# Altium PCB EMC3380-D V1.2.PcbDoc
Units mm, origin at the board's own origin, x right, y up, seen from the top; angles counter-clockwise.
Board outline 20 x 33 mm, 2 copper layers (Top Layer, Bottom Layer); 70 components, 71 nets, 338 pads, 271 vias.
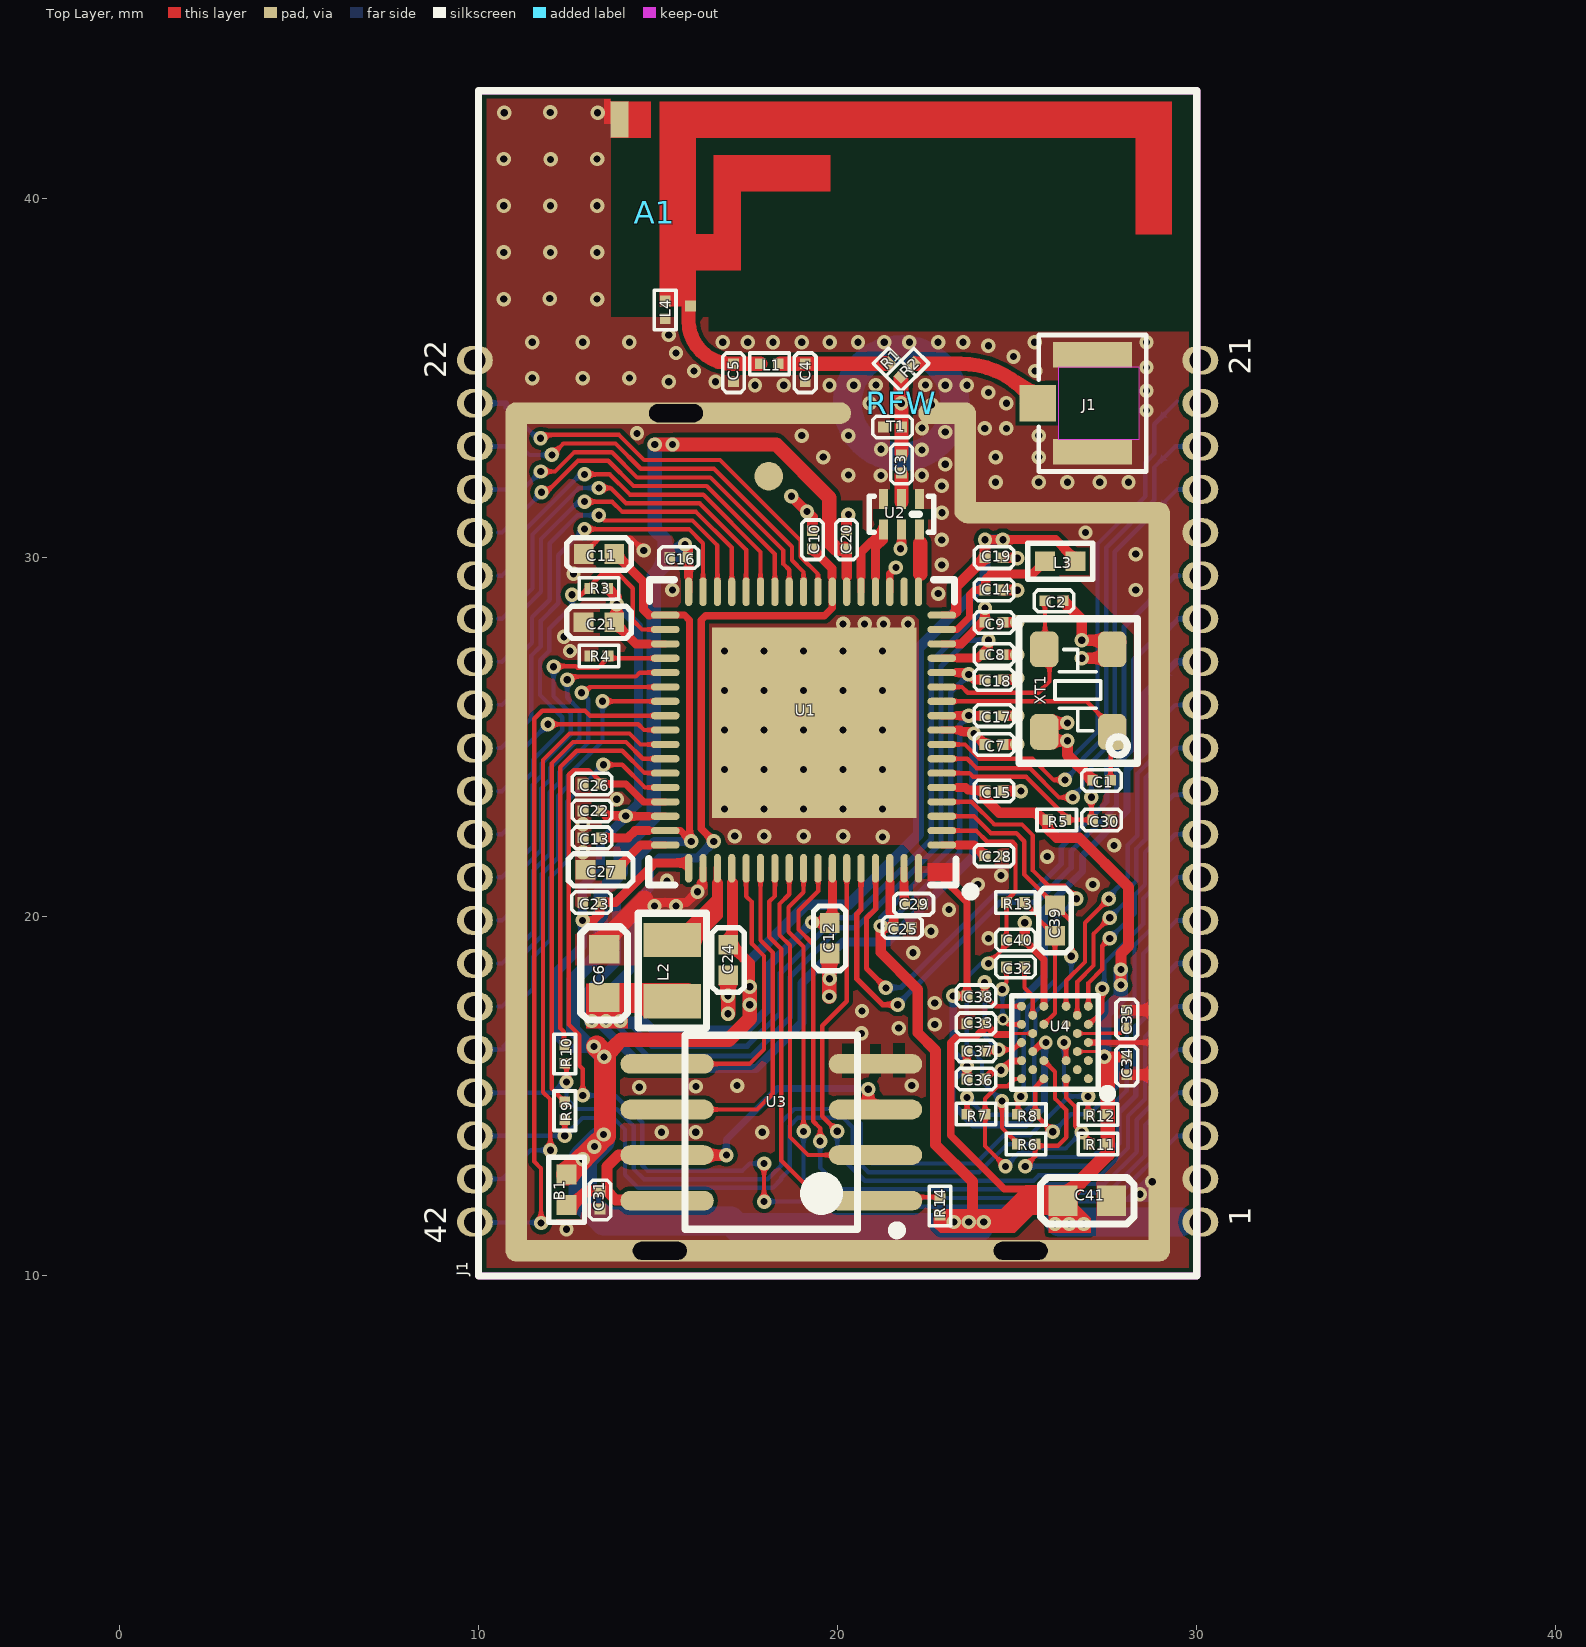
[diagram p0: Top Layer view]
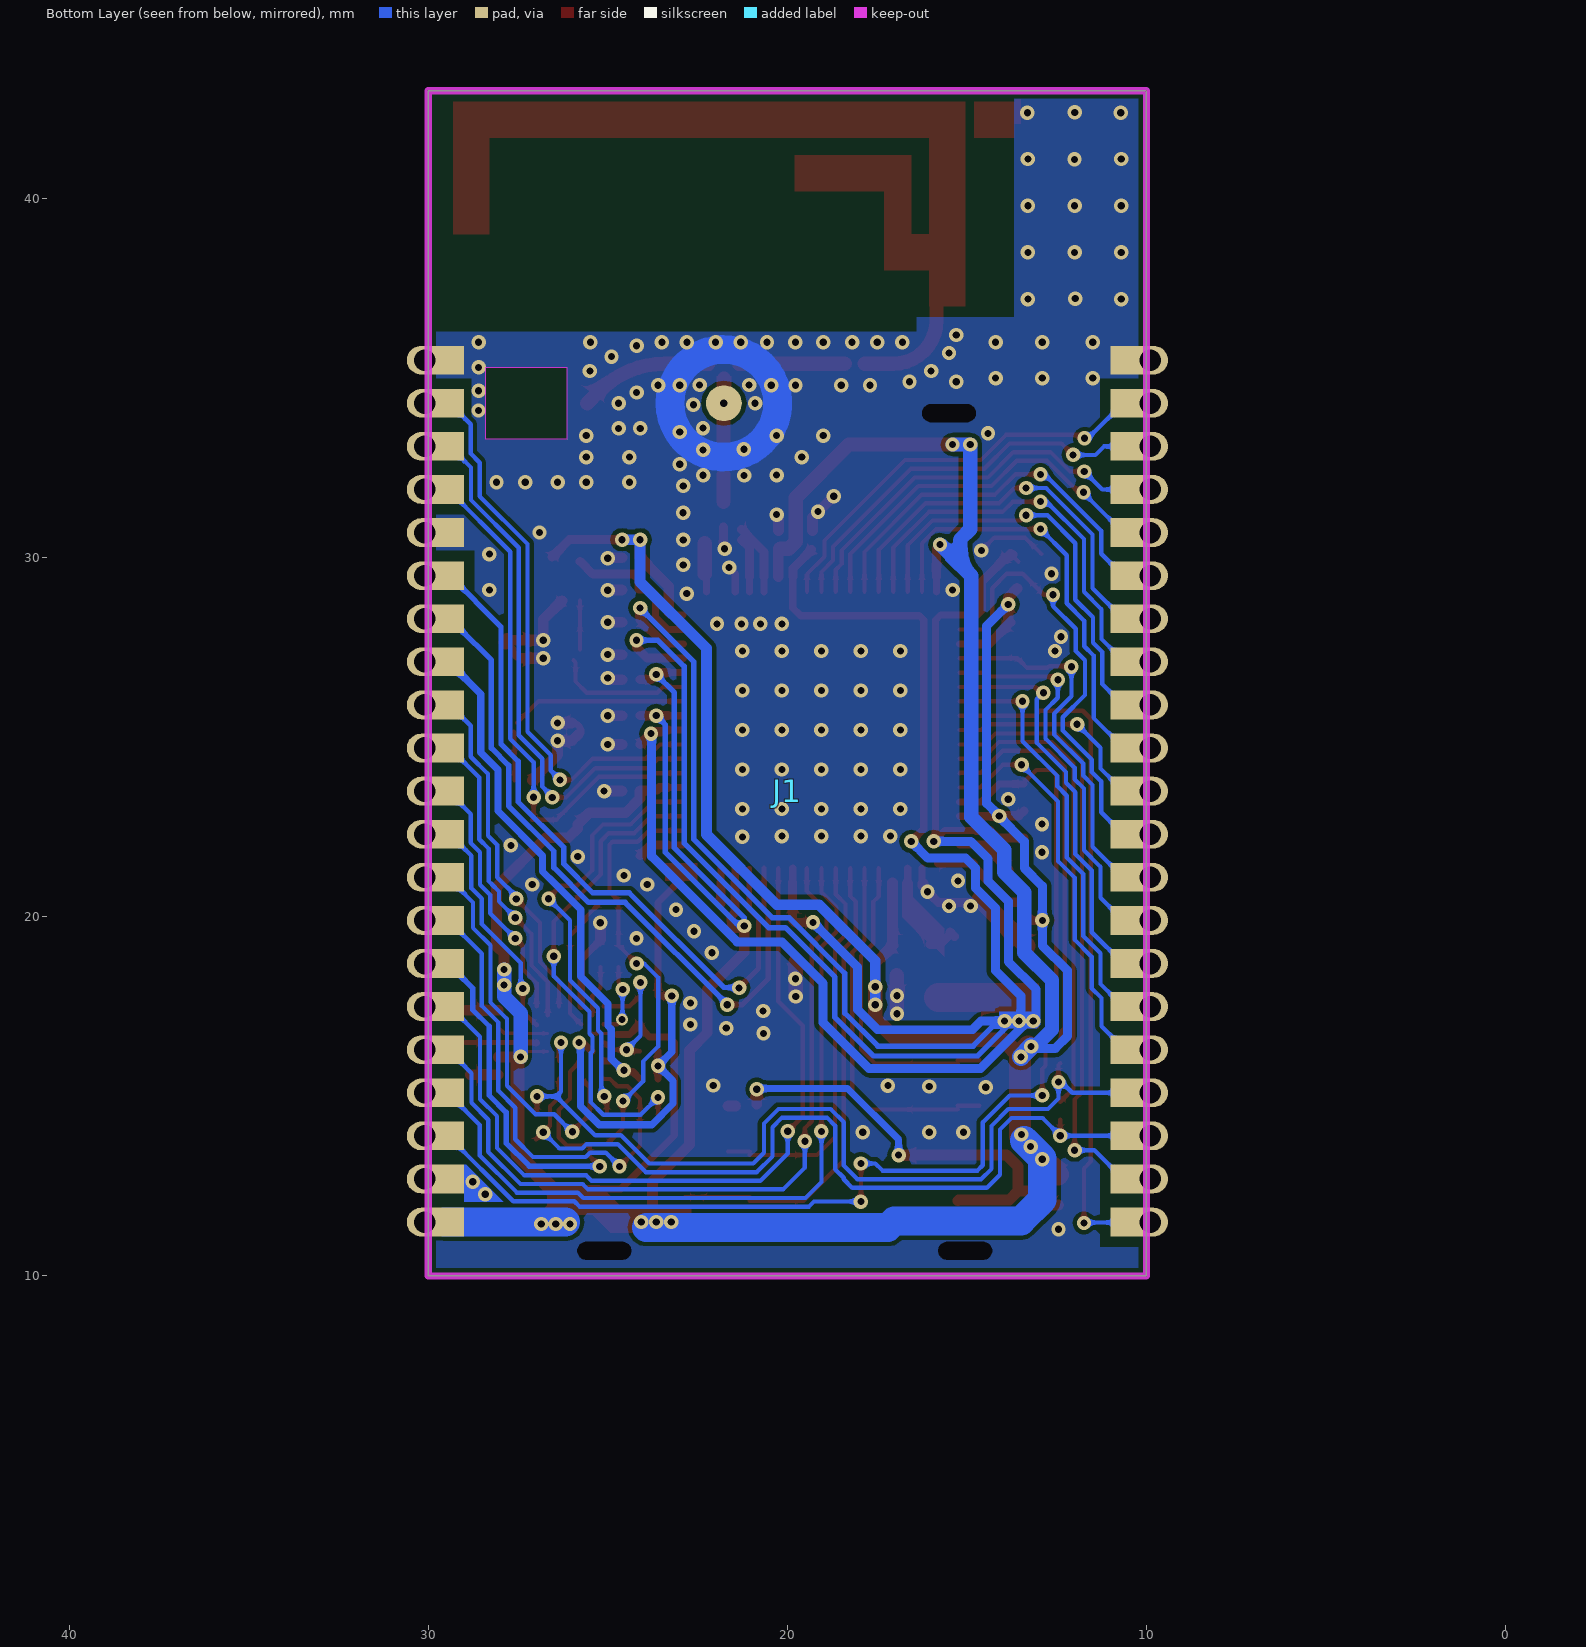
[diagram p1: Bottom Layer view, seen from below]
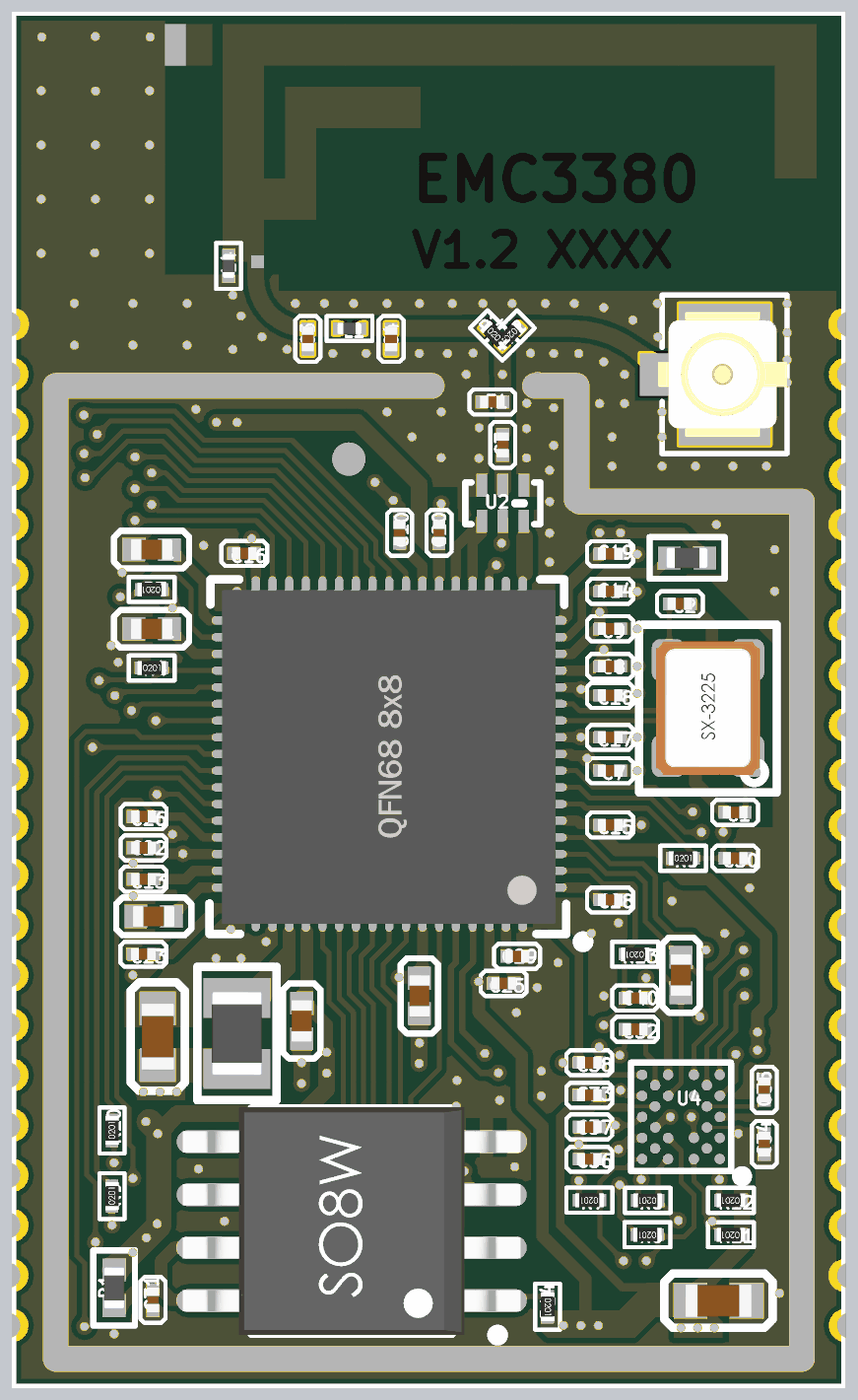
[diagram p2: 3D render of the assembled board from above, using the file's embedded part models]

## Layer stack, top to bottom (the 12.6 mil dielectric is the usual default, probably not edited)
Top Solder: solder mask 0.0102, Solder Resist, Dk 3.5
Top Layer: signal copper 0.0356
Dielectric 1: dielectric 0.32, FR-4, Dk 4.8
Bottom Layer: signal copper 0.0356
Bottom Solder: solder mask 0.0102, Solder Resist, Dk 3.5

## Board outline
29.997,10 29.997,43 10,43 10,10

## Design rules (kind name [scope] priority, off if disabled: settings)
Clearance [All] p1: gap=0.12 ignorepadtopadclearanceinfootprint=FALSE
ComponentClearance [All] p1: gap=0 collisioncheckmode=3 verticalgap=0 showdistances=FALSE
PolygonConnect [All] p1: connectstyle=Direct reliefconductorwidth=0.254 reliefentries=4 polygonreliefangle="90 Angle" airgapwidth=0.254
RoutingVias [All] p1: holewidth=0.2 width=0.4 viastyle="Through Hole" minholewidth=0.1 minwidth=0.3 maxholewidth=0.711 maxwidth=1.27
SolderMaskExpansion [All] p1: expansion=0.01 istentingtop=FALSE
Width [All] p1: maxlimit=1 minlimit=0.1 preferedwidth=0.12 minimp=50.000000 maximp=50.000000 favimp=50.000000
29 further rules are at their usual default settings.

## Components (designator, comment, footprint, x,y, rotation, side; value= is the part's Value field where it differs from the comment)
A1 "PCB ANT" ANT1607-2.4/5G 22.049,40 r0 top locked
B1 "200R" IND0402-1005L 12.45,12.4 r90 top
C1 "10pF,50V,NP" CAP0201-0603L#1 27.349,23.8 r180 top
C2 "10pF,50V,NP" CAP0201-0603L#1 26.023,28.8 r180 top
C3 "10pF,50V" CAP0201-0603L#1 21.775,32.61 r90 top value=100pF
C4 "1.5pF,50V,NP" CAP0201-0603L#2 19.095,35.15 r270 top value=100pF
C5 "0.5pF,50V,NP" CAP0201-0603L#2 17.097,35.15 r270 top value=100pF
C6 "10uF,10V" CAP0603-1608L 13.497,18.425 r270 top value=100pF
C7 "100nF,10V" CAP0201-0603L#1 24.35,24.8 r0 top value=100pF
C8 "100nF,10V" CAP0201-0603L#1 24.35,27.3 r0 top value=100pF
C9 "100nF,10V" CAP0201-0603L#1 24.35,28.2 r0 top value=100pF
C10 "100nF,10V" CAP0201-0603L#1 19.297,30.5 r90 top value=100pF
C11 "2.2uF,10V" CAP0402-1005L 13.35,30.1 r180 top value=100pF
C12 "2.2uF,10V" CAP0402-1005L 19.776,19.401 r270 top value=100pF
C13 "100nF,10V" CAP0201-0603L#1 13.157,22.2 r180 top value=100pF
C14 "100nF,10V" CAP0201-0603L#1 24.35,29.1 r0 top value=100pF
C15 "100nF,10V" CAP0201-0603L#1 24.35,23.5 r0 top value=100pF
C16 "100nF,10V" CAP0201-0603L#1 15.573,30.006 r180 top value=100pF
C17 "100nF,10V" CAP0201-0603L#1 24.35,25.6 r0 top value=100pF
C18 "100nF,10V" CAP0201-0603L#1 24.35,26.604 r0 top value=100pF
C19 "100nF,10V" CAP0201-0603L#1 24.35,30 r0 top value=100pF
C20 "100nF,10V" CAP0201-0603L#1 20.247,30.5 r90 top value=100pF
C21 "2.2uF,10V" CAP0402-1005L 13.35,28.2 r180 top value=100pF
C22 "100nF,10V" CAP0201-0603L#1 13.157,22.95 r180 top value=100pF
C23 "100nF,10V" CAP0201-0603L#1 13.15,20.4 r180 top value=100pF
C24 "2.2uF,10V" CAP0402-1005L 16.95,18.8 r270 top value=100pF
C25 "1uF,10V" CAP0201-0603L#1 21.797,19.7 r0 top value=100pF
C26 "100nF,10V" CAP0201-0603L#1 13.157,23.7 r180 top value=100pF
C27 "2.2uF,10V" CAP0402-1005L 13.4,21.307 r180 top value=100pF
C28 "4.7nF,10V" CAP0201-0603L#1 24.35,21.7 r0 top value=100pF
C29 "1uF,10V" CAP0201-0603L#1 22.117,20.35 r0 top value=100pF
C30 "22nF,10V,NP" CAP0201-0603L#1 27.35,22.7 r0 top value=100pF
C31 "100nF,10V" CAP0201-0603L#1 13.38,12.112 r90 top value=100pF
C32 "100nF,10V" CAP0201-0603L#1 24.95,18.6 r180 top value=100pF
C33 "1uF,10V" CAP0201-0603L#1 23.85,17.02 r180 top value=100pF
C34 "1uF,10V" CAP0201-0603L#1 28.05,15.85 r270 top value=100pF
C35 "1uF,10V" CAP0201-0603L#1 28.05,17.15 r90 top value=100pF
C36 "1uF,10V" CAP0201-0603L#1 23.85,15.484 r180 top value=100pF
C37 "1uF,10V" CAP0201-0603L#1 23.85,16.26 r180 top value=100pF
C38 "1uF,10V" CAP0201-0603L#1 23.85,17.8 r180 top value=100pF
C39 "2.2uF,10V" CAP0402-1005L 26.05,19.9 r90 top value=100pF
C40 "1uF,10V" CAP0201-0603L#1 24.95,19.351 r0 top value=100pF
C41 "10uF,10V" CAP0603-1608L 26.95,12.095 r180 top value=100pF
J1 "EMW3380DM" EMW3380-2 9.997,10 r0 top locked
J1 "IPEX" IPEX-0.7X2.2 27.197,34.3 r270 top
L1 "0R,5%" IND0201-0603L#1 18.097,35.4 r180 top
L2 "2.2uH" IND0805-2012L 15.397,18.5 r270 top
L3 "4.7nH" IND0402-1005L 26.197,29.9 r0 top
L4 "2.7nH" IND0201-0603L#2 15.197,36.9 r90 top
R1 "0R,5%" RES0201-0603L#1 21.589,35.233 r315 top
R2 "0R,5%,NP" RES0201-0603L#1 21.939,35.233 r225 top
R3 "10K,5%" RES0201-0603L#2 13.35,29.143 r180 top
R4 "12K,1%,NP" RES0201-0603L#2 13.35,27.261 r0 top
R5 "10K,5%" RES0201-0603L#2 26.1,22.7 r0 top
R6 "0R,5%" RES0201-0603L#2 25.247,13.675 r180 top
R7 "0R,5%" RES0201-0603L#2 23.854,14.505 r180 top
R8 "0R,5%" RES0201-0603L#2 25.25,14.5 r180 top
R9 "0R,5%" RES0201-0603L#2 12.4,14.6 r90 top
R10 "0R,5%" RES0201-0603L#2 12.4,16.175 r90 top
R11 "10K,5%" RES0201-0603L#2 27.247,13.675 r180 top
R12 "10K,5%" RES0201-0603L#2 27.25,14.5 r180 top
R13 "2.2K,5%" RES0201-0603L#2 24.95,20.4 r180 top
R14 "10KR,5%" RES0201-0603L#2 22.85,11.95 r270 top
RFW "BNC" "RF Test" 21.767,34.3 r90 top locked
T1 "TVS" CAP0201-0603L#1 21.525,33.639 r180 top
U1 "RTL8721DM" QFN68-8X8-P040L 19.05,25.2 r180 top locked
U2 "RFDIP1606L248D1T" FT1608-6-P050N 21.775,31.21 r180 top
U3 "BY25Q32B" SOP8W-P127L 18.15,14 r180 top
U4 "BR262" WLCSP26-P050 26.05,16.5 r90 top
XT1 "40MHz" OSC3225L 26.697,26.3 r90 top locked

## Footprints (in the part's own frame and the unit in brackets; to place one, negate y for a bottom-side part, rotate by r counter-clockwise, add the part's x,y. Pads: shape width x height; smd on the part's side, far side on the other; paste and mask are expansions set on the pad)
ANT1607-2.4/5G [mm]
  rect 0.305x0.305 smd mask+0: 1(-6.153,-2.998)
  rect 0.305x0.305 smd: 2(-6.851,-2.847)
  rect 0.5x1 smd mask+0: 3(-8.13,2.2)
  Top Layer region: -7,2.7 -7,-3 -6,-3 -6,-2 -4.75,-2 -4.75,0.2 -2.25,0.2 -2.25,1.2 -5.5,1.2 -5.5,-1 -6,-1 -6,1.7 6.25,1.7 6.25,-1 7.25,-1 7.25,2.7
  Top Layer region: -8.375,2.7 -8.375,1.7 -7.25,1.7 -7.25,2.7
  Top Layer pour cut-out: -8.375,2.95 8,2.95 8,-3.702 -5.65,-3.702 -5.65,-3.302 -8.375,-3.302
  Bottom Layer pour cut-out: -8.375,2.95 -8.375,-3.302 -5.65,-3.302 -5.65,-3.702 8,-3.702 8,2.95
CAP0201-0603L#1 [mm] "Chip Capacitor, 2-Leads, Body 0.60x0.30mm, IPC High Density"
  rect 0.3x0.3 smd: 1(-0.25,0) 2(0.25,0)
  Top Layer pour cut-out: 0.102,0.178 -0.102,0.178 -0.102,-0.178 0.102,-0.178
  silkscreen extent -0.55,-0.3 0.55,0.3, body extent -0.3,-0.15 0.3,0.15, height 0.3
CAP0201-0603L#2 [mm] "Chip Capacitor, 2-Leads, Body 0.60x0.30mm, IPC High Density"
  rect 0.3x0.3 smd mask+0.05: 1(-0.25,0) 2(0.25,0)
  Top Layer pour cut-out: 0.102,0.178 -0.102,0.178 -0.102,-0.178 0.102,-0.178
  silkscreen extent -0.55,-0.3 0.55,0.3, body extent -0.3,-0.15 0.3,0.15, height 0.3
CAP0402-1005L [mm] "Chip Capacitor, 2-Leads, Body 1.00x0.50mm, IPC High Density"
  rect 0.55x0.55 smd: 1(-0.425,0) 2(0.425,0)
  silkscreen extent -0.9,-0.45 0.9,0.45, body extent -0.5,-0.25 0.5,0.25, height 0.5
CAP0603-1608L [mm] "Chip Capacitor, 2-Leads, Body 1.60x0.80mm, IPC High Density"
  rect 0.8x0.85 smd: 1(-0.675,0) 2(0.675,0)
  silkscreen extent -1.3,-0.65 1.3,0.65, body extent -0.8,-0.4 0.8,0.4, height 0.6
EMW3380-2 [mm] "Footprint of EMW3030"
  rect 1x0.8 smd far side: 1(19.5,1.5) 2(19.5,2.7) 3(19.5,3.9) 4(19.5,5.1) 5(19.5,6.3) 6(19.5,7.5) 7(19.5,8.7) 8(19.5,9.9) 9(19.5,11.1) 10(19.5,12.3) 11(19.5,13.5) 12(19.5,14.7) 13(19.5,15.9) 14(19.5,17.1) 15(19.5,18.3) 16(19.5,19.5) 17(19.5,20.7) 18(19.5,21.9) 19(19.5,23.1) 20(19.5,24.3) 21(19.5,25.5) 22(0.5,25.5) 23(0.5,24.3) 24(0.5,23.1) 25(0.5,21.9) 26(0.5,20.7) 27(0.5,19.5) 28(0.5,18.3) 29(0.5,17.1) 30(0.5,15.9) 31(0.5,14.7) 32(0.5,13.5) 33(0.5,12.3) 34(0.5,11.1) 35(0.5,9.9) 36(0.5,8.7) 37(0.5,7.5) 38(0.5,6.3) 39(0.5,5.1) 40(0.5,3.9) 41(0.5,2.7) 42(0.5,1.5)
  oval 1x0.8 hole 0.6: 1(20.1,1.5) 2(20.1,2.7) 3(20.1,3.9) 4(20.1,5.1) 5(20.1,6.3) 6(20.1,7.5) 7(20.1,8.7) 8(20.1,9.9) 9(20.1,11.1) 10(20.1,12.3) 11(20.1,13.5) 12(20.1,14.7) 13(20.1,15.9) 14(20.1,17.1) 15(20.1,18.3) 16(20.1,19.5) 17(20.1,20.7) 18(20.1,21.9) 19(20.1,23.1) 20(20.1,24.3) 21(20.1,25.5) 22(-0.1,25.5) 23(-0.1,24.3) 24(-0.1,23.1) 25(-0.1,21.9) 26(-0.1,20.7) 27(-0.1,19.5) 28(-0.1,18.3) 29(-0.1,17.1) 30(-0.1,15.9) 31(-0.1,14.7) 32(-0.1,13.5) 33(-0.1,12.3) 34(-0.1,11.1) 35(-0.1,9.9) 36(-0.1,8.7) 37(-0.1,7.5) 38(-0.1,6.3) 39(-0.1,5.1) 40(-0.1,3.9) 41(-0.1,2.7) 42(-0.1,1.5)
  silkscreen extent 0,0 20,33
FT1608-6-P050N [mm]
  rect 0.25x0.55 smd: 1(-0.5,-0.425) 2(0,-0.425) 3(0.5,-0.425) 4(0.5,0.425) 5(0,0.425) 6(-0.5,0.425)
  silkscreen extent -0.9,-0.5 0.9,0.5, body extent -0.9,-0.5 0.9,0.5, height 0.71
IND0201-0603L#1 [mm] "Chip Inductor, 2-Leads, Body 0.60x0.30mm, IPC High Density"
  rect 0.3x0.3 smd mask+0.05: 1(-0.25,0) 2(0.25,0)
  Top Layer pour cut-out: 0.102,0.178 -0.102,0.178 -0.102,-0.178 0.102,-0.178
  silkscreen extent -0.55,-0.3 0.55,0.3, body extent -0.3,-0.15 0.3,0.15, height 0.3
IND0201-0603L#2 [mm] "Chip Inductor, 2-Leads, Body 0.60x0.30mm, IPC High Density"
  rect 0.3x0.3 smd: 1(-0.25,0) 2(0.25,0)
  silkscreen extent -0.55,-0.3 0.55,0.3, body extent -0.3,-0.15 0.3,0.15, height 0.3
IND0402-1005L [mm] "Chip Inductor, 2-Leads, Body 1.00x0.50mm, IPC High Density"
  rect 0.55x0.55 smd: 1(-0.425,0) 2(0.425,0)
  silkscreen extent -0.9,-0.5 0.9,0.5, body extent -0.5,-0.25 0.5,0.25, height 0.4
IND0805-2012L [mm] "Chip Inductor, 2-Leads, Body 2.00x1.25mm, IPC High Density"
  rect 0.95x1.6 smd: 1(-0.85,0) 2(0.85,0)
  silkscreen extent -1.6,-0.95 1.6,0.95, body extent -1,-0.6 1,0.6, height 0.6
IPEX-0.7X2.2 [mm]
  rect 1.016x1.016 smd mask+0.05: 1(0.001,-1.625)
  rect 0.7x2.2 smd mask+0.05: 2(1.351,-0.1) 3(-1.349,-0.1)
  Keep-Out Layer pour cut-out: -0.999,-1.05 0.999,-1.05 0.999,1.2 -0.999,1.2
  silkscreen extent -1.9,-1.6 1.9,1.4, body extent -1.5,-1.7 1.5,1.4, height 1.25
OSC3225L [mm]
  rrect50% 1x0.8 smd: 1(-1.15,-0.95) 2(1.15,-0.95) 3(1.15,0.947) 4(-1.15,0.947)
  silkscreen extent -2.02,-1.65 2,1.65, body extent -1.6,-1.25 1.6,1.25, height 0.81
QFN68-8X8-P040L [mm] "QFN, 68-Leads, Body 8.00x8.00mm, Pitch 0.40mm, Thermal Pad 5.50x5.50mm, IPC High Density"
  oval 0.8x0.2 smd: 1(-3.85,3.2) 2(-3.85,2.8) 3(-3.85,2.4) 4(-3.85,2) 5(-3.85,1.6) 6(-3.85,1.2) 7(-3.85,0.8) 8(-3.85,0.4) 9(-3.85,0) 10(-3.85,-0.4) 11(-3.85,-0.8) 12(-3.85,-1.2) 13(-3.85,-1.6) 14(-3.85,-2) 15(-3.85,-2.4) 16(-3.85,-2.8) 17(-3.85,-3.2) 35(3.85,-3.2) 36(3.85,-2.8) 37(3.85,-2.4) 38(3.85,-2) 39(3.85,-1.6) 40(3.85,-1.2) 41(3.85,-0.8) 42(3.85,-0.4) 43(3.85,0) 44(3.85,0.4) 45(3.85,0.8) 46(3.85,1.2) 47(3.85,1.6) 48(3.85,2) 49(3.85,2.4) 50(3.85,2.8) 51(3.85,3.2)
  oval 0.2x0.8 smd: 18(-3.2,-3.85) 19(-2.8,-3.85) 20(-2.4,-3.85) 21(-2,-3.85) 22(-1.6,-3.85) 23(-1.2,-3.85) 24(-0.8,-3.85) 25(-0.4,-3.85) 26(0,-3.85) 27(0.4,-3.85) 28(0.8,-3.85) 29(1.2,-3.85) 30(1.6,-3.85) 31(2,-3.85) 32(2.4,-3.85) 33(2.8,-3.85) 34(3.2,-3.85) 52(3.2,3.85) 53(2.8,3.85) 54(2.4,3.85) 55(2,3.85) 56(1.6,3.85) 57(1.2,3.85) 58(0.8,3.85) 59(0.4,3.85) 60(0,3.85) 61(-0.4,3.85) 62(-0.8,3.85) 63(-1.2,3.85) 64(-1.6,3.85) 65(-2,3.85) 66(-2.4,3.85) 67(-2.8,3.85) 68(-3.2,3.85)
  rect 5.7x5.3 smd: 69(-0.3,-0.2)
  silkscreen extent -4.77,-4.18 4.31,4.63, body extent -3.99,-3.94 4.01,4.07, height 0.88
RES0201-0603L#1 [mm] "Chip Resistor, 2-Leads, Body 0.60x0.30mm, IPC High Density"
  rect 0.3x0.3 smd mask+0.05: 1(-0.25,0) 2(0.25,0)
  Top Layer pour cut-out: 0.102,0.178 -0.102,0.178 -0.102,-0.178 0.102,-0.178
  silkscreen extent -0.55,-0.3 0.55,0.3, body extent -0.34,-0.16 0.34,0.17, height 0.34
RES0201-0603L#2 [mm] "Chip Resistor, 2-Leads, Body 0.60x0.30mm, IPC High Density"
  rect 0.3x0.3 smd: 1(-0.25,0) 2(0.25,0)
  Top Layer pour cut-out: 0.102,0.178 -0.102,0.178 -0.102,-0.178 0.102,-0.178
  silkscreen extent -0.55,-0.3 0.55,0.3, body extent -0.34,-0.16 0.34,0.17, height 0.34
"RF Test" [mil]
  round 16 / inner round 16 / far side round 39.37 hole 8 mask+1.97: 1(0,0)
  Bottom Layer circle w31.5: c0,0 r59.06
SOP8W-P127L [mm] "SOIC, 8-Leads, Body 5.28x5.28mm, Pitch 1.27mm, IPC High Density"
  oval 2.6x0.55 smd: 1(-2.9,1.905) 2(-2.9,0.635) 3(-2.9,-0.635) 4(-2.9,-1.905) 5(2.9,-1.905) 6(2.9,-0.635) 7(2.9,0.635) 8(2.9,1.905)
  silkscreen extent -3.63,-2.7 2.4,2.85, body extent -4.05,-2.73 4.05,2.73, height 1.75
WLCSP26-P050 [mm] "WLCSP26, 2.388x2.233"
  round 0.25 smd: A1(-1.008,-0.93) A3(-0.504,-0.93) A5(0,-0.93) A7(0.504,-0.93) A9(1.008,-0.93) B2(-0.756,-0.62) B4(-0.252,-0.62) B6(0.252,-0.62) B8(0.756,-0.62) C1(-1.008,-0.31) C3(-0.504,-0.31) C7(0.504,-0.31) C9(1.008,-0.31) E1(-1.008,0.31) E3(-0.504,0.31) E7(0.504,0.31) E9(1.008,0.31) F2(-0.756,0.62) F4(-0.252,0.62) F6(0.252,0.62) F8(0.756,0.62) G1(-1.008,0.93) G3(-0.504,0.93) G5(0,0.93) G7(0.504,0.93) G9(1.008,0.93)
  silkscreen extent -1.3,-1.2 1.3,1.2, body extent -1.2,-1.1 1.2,1.1, height 1.01

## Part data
A1: library part "ANTENNA Right", "2.4G PCB ANTENNA Right"
B1 L1 L2 L3 L4: library part Inductor, "Inductor"
C1 C2: library part CAP, "Capacitor"
C3 C4 C5 C6 C7 C8 C9 C10 C11 C12 C13 C14 C15 C16 C17 C18 C19 C20 C21 C22 C23 C24 C25 C26 C27 C28 C29 C30 C31 C32 C33 C34 C35 C36 C37 C38 C39 C40 C41: library part Cap, "Capacitor", Manufacturer=muRata
J1: library part EMW3380
J1: library part IPEX_ANT
R1 R2 R3 R4 R5 R6 R7 R8 R9 R10 R11 R12 R13 R14: library part RES1
RFW: "BNC Elbow Connector"
T1: library part DR, "瞬态电压抑制二极管"
U1: library part "Ameba D"
U2: library part SGM2036-3.3
U3: library part M25P80S-VMN6P, "8 Mb (x1) Serial NOR Flash Memory, 75 MHz, 2.7 to 3.6 V, 8-pin SO8 Narrow (MN), Tube", Manufacturer=Micron, Package="SO8 Narrow?", Voltage=2.7V-3.6V?
XT1: library part CRYS_24MHz_CS325, "Crystal 24MHz", Manufacturer=凯越翔, PartName=Crystal24MHzSCC, TIIntPartnumber=1Y0033

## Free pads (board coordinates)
  oval 0.6x23.9 smd: 0(11.047,22.375)
  oval 1.2x0.5 hole 0.5 slot 1.5 at 0 deg: 0(15.047,10.7) 0(25.097,10.7)
  oval 1.2x0.5 hole 0.5 slot 1.5 at 0 deg mask+0.05: 0(15.497,34.025)
  oval 18.5x0.6 smd: 0(20,10.7)
  oval 1.6x0.6 smd: 0(23.047,34.025) 2(23.047,34.025)
  oval 0.6x3.3 smd: 0(23.547,32.65)
  oval 5.9x0.6 smd: 0(26.275,31.25)
  oval 0.6x21.1 smd: 0(28.95,21)
  round 0.8 smd: 1(18.08,32.269)
  oval 9.6x0.6 smd: 2(15.572,34.025)

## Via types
v1: diameter 0.4, hole 0.2, Top Layer to Bottom Layer, tented both sides, 268 vias
v2: diameter 0.38, hole 0.2, Top Layer to Bottom Layer, tented both sides, 2 vias
v3: diameter 0.34, hole 0.2, Top Layer to Bottom Layer, tented both sides, 1 vias

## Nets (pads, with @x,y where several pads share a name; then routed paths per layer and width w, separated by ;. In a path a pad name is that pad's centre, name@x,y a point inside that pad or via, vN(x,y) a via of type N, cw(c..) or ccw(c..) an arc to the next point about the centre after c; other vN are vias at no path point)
AGND: C36.2 C37.2 C38.2 U4.F4 | length 13.5
  Top Layer w0.1: U4.F4 U4.F4@25.442,16.26
  Top Layer w0.2: 22.8,21.2 23.6,20.4 C38.2 23.598,17.798 v1(23.217,17.798) ; C36.2 C37.2 ; U4.F4@25.442,16.26 25.444,16.258 25.453,16.258 25.661,16.466 25.762,16.466 v2(25.796,16.5)
  Bottom Layer w0.2: v1(23.217,17.798) 23.217,16.233 v1(23.6,15.85) 23.182,15.432 23.182,14.798 23.771,14.209 25.239,14.209 25.757,14.727 25.757,16.46 v2(25.796,16.5)
ALPHA_SEL: J1.13 U4.C9 | length 10.3
  Top Layer w0.12: U4.C9 26.36,18.218 26.885,18.743 26.885,19.835 v1(27.55,20.5)
  Bottom Layer w0.12: v1(27.55,20.5) v1@27.55,20.565 ; v1@27.55,20.571 28.077,21.098 28.077,21.998 28.337,22.258 28.337,23.979 28.817,24.459 28.817,25.32 29.397,25.9 29.497,25.9 J1.13@30.097,25.9
BOOT_SEL: J1.11 U4.A9 | length 7.3
  Top Layer w0.12: U4.A9 26.98,18.159 27.365,18.544 27.365,19.19 v1(27.575,19.4)
  Bottom Layer w0.12: v1(27.575,19.4) 28.27,20.095 28.27,20.606 28.557,20.893 28.557,21.799 28.817,22.059 28.817,22.859 29.358,23.4 J1.11@29.75,23.4
CHAN_SEL: J1.12 U4.B8 | length 8.9
  Top Layer w0.12: U4.B8 26.67,18.188 27.125,18.643 27.125,19.525 v1(27.575,19.975)
  Bottom Layer w0.12: v1(27.575,19.975) 28.03,20.43 28.03,20.706 28.229,20.905 28.229,20.911 28.317,20.999 28.317,21.899 28.577,22.159 28.577,23.88 29.057,24.36 29.397,24.7 J1.12@29.767,24.7
CLOCK_SEL: J1.10 U4.A7 | length 6.7
  Top Layer w0.12: U4.A7 26.98,16.982 27.365,17.367 v1(27.365,18)
  Bottom Layer w0.12: v1(27.365,18) 27.425,18.06 27.425,18.713 28.51,19.798 28.51,20.507 28.797,20.794 28.797,21.7 29.397,22.3 29.497,22.3 J1.10@29.75,22.3
GND: A1.3 C1.2 C2.1 C4.2 C5.2 C6.1 C7.2 C8.2 C9.2 C10.2 C11.2 C12.2 C13.2 C14.2 C15.2 C16.2 C17.2 C18.2 C19.2 C20.2 C21.2 C22.2 C23.2 C24.2 C25.2 C26.2 C27.2 C28.2 C29.2 C30.2 C31.1 C33.2 C34.2 C35.2 C40.2 C41.1 J1.2 J1.3@27.097,35.649 J1.17 J1.21 J1.22 L4.1 pad.0 pad.2 R4.1 T1.2 U1.20 U1.53 U1.68 U1.69 U2.1 U2.3 U2.5 U3.4 U4.A5 U4.E9 XT1.2 XT1.4 | length 26.5
  Top Layer w0.12: C11.2 13.38,30.555 14.242,30.555 v1(14.597,30.2) ; C40.2 C40.2@25.211,19.34
  Top Layer w0.15: U4.A5 pad.0@28.95,16.5
  Top Layer w0.2: 16.25,20.928 U1.53 ; C12.2@19.769,18.744 C12.2@19.775,18.75 ; U1.20 21.45,29.556 v1(21.621,29.726) ; C40.2 C40.2@25.205,19.356 ; v1@25.205,19.827 v1(25.211,19.832) ; C40.2@25.211,19.34 25.74,18.811 U4.E9 ; XT1.4@25.747,25.104 25.747,25.15 cw(c25.997,25.15) XT1.4@25.997,25.4 ; U4.A5 U4.A5@26.99,16.49 ; XT1.2@27.397,27.2 ccw(c27.397,27.45) XT1.2
  Top Layer w0.25: 14.625,20.4 15.797,20.4 v1(16.097,20.7) ; U2.5@21.775,30.859 21.779,30.856 v1@21.779,30.363
  Top Layer w0.3: 16.222,20.866 16.222,20.93 ; v1(18.709,31.712) 19.297,31.125 C10.2 ; C20.2 v1@20.247,31.2 ; C15.2 v1@25,23.5 ; C7.2 v1@24.997,24.8 ; C17.2 v1@24.997,25.6 ; C18.2 v1@25,26.604 ; C8.2 v1@24.997,27.3 ; C9.2 v1(25,28.2) ; C14.2 v1@24.997,29.1 ; C19.2 v1@25,30 ; C40.2@25.205,19.356 v1@25.205,19.827 ; XT1.4@25.824,25.075 25.999,24.9 v1(26.397,24.9) 26.397,24.502 C1.2 ; XT1.4@25.997,25.4 v1(26.397,25.4) ; C2.1 26.797,28.276 v1(26.797,27.7) XT1.2@27.797,27.7 ; v1(26.797,27.2) XT1.2@27.397,27.2 ; C34.2 pad.0@28.828,15.6 ; C35.2 pad.0@28.95,17.4
  Top Layer w0.4: v1@16.95,17.3 C24.2 ; v1@19.767,18.42 19.767,18.743 C12.2@19.769,18.744 ; v1@19.769,17.778 v1@19.769,18.374 ; XT1.2@27.797,27.7 XT1.2@27.847,27.65
  Top Layer w0.5: C6.1@13.333,19.189 14.621,20.477
  other v1: 12.45,11.3 28.413,12.274 28.76,12.624 15.097,14 16.048,14.003 17.9,14 14.475,15.253 16.05,15.275 17.2,15.3 22.06,15.305 20.663,16.754 21.7,16.9 22.7,17 16.947,17.3 20.675,17.376 22.7,17.6 19.767,17.78 16.947,17.8 19.775,18.275 22.1,19 24.2,19.4 22.6,19.6 23.1,20.2 14.897,20.3 15.497,20.3 23.9,20.9 27.1,20.9 15.247,21 24.55,21.15 25.834,21.675 12.907,21.8 27.697,21.989 21.25,22.225 17.131,22.246 17.95,22.246 19.05,22.246 20.15,22.246 12.907,22.58 16.85,23 17.95,23 19.05,23 20.15,23 21.25,23 13.85,23.273 25.1,23.5 16.85,24.1 17.95,24.1 19.05,24.1 20.15,24.1 21.25,24.1 25,24.8 16.85,25.2 17.95,25.2 19.05,25.2 20.15,25.2 21.25,25.2 25,25.6 16.85,26.3 17.95,26.3 19.05,26.3 20.15,26.3 21.25,26.3 25,26.65 25,27.3 12.547,27.4 16.85,27.4 17.95,27.4 19.05,27.4 20.15,27.4 21.25,27.4 12.377,27.8 20.15,28.156 20.75,28.156 21.275,28.156 21.958,28.156 22.8,29 25,29.095 15.397,29.1 28.297,29.1 12.643,29.55 22.897,29.8 25,29.987 28.297,30.1 21.747,30.25 22.897,30.496 26.9,30.7 20.297,31.2 22.9,31.25 19.146,31.282 22.897,32 24.397,32.1 25.597,32.1 26.397,32.1 27.297,32.1 28.097,32.1 21.202,32.288 22.345,32.296 20.297,32.3 22.997,32.6 19.597,32.8 24.397,32.8 25.597,32.8 22.345,33.001 21.21,33.021 18.997,33.4 20.297,33.4 25.597,33.4 14.411,33.461 22.997,33.5 22.349,33.609 24.097,33.6 24.697,33.6 28.6,34.1 22.614,34.259 20.897,34.3 24.697,34.3 24.197,34.6 28.597,34.65 17.697,34.8 18.497,34.8 19.772,34.8 20.447,34.8 21.064,34.809 22.441,34.809 22.997,34.8 23.597,34.8 15.297,34.9 16.597,34.9 11.497,35 12.9,35 14.2,35 15.997,35.2 25.497,35.2 28.597,35.3 24.897,35.6 15.497,35.7 24.197,35.9 11.497,36 12.9,36 14.2,36 16.797,36 17.497,36 18.197,36 18.997,36 19.775,36 20.564,36 21.297,36 21.997,36 22.797,36 23.492,36 25.484,36 28.597,36 15.297,36.2 10.7,37.2 11.983,37.213 13.3,37.2 10.7,38.5 12,38.5 13.3,38.5 10.7,39.8 12,39.8 13.3,39.8 10.7,41.1 12.005,41.09 13.3,41.1 10.714,42.387 11.997,42.4 13.314,42.387
I2C_SCL: J1.40 R9.1 R11.2 U4.C1 | length 24.3
  Top Layer w0.12: v1(12.4,13.904) R9.1 ; U4.C1 26.36,14.967 26.606,14.721 26.606,14.191 v1(26.797,14) ; v1@26.797,14.049 v1(26.797,14) ; R11.2@26.997,13.8 v1(26.797,14)
  Bottom Layer w0.12: J1.40@9.95,13.9 10.73,13.9 10.734,13.904 v1(12.4,13.904) 12.891,14.395 13.758,14.395 14.077,14.077 14.077,12.82 14.444,12.452 18.192,12.452 18.43,12.691 18.43,12.735 18.669,12.973 18.669,14.183 18.893,14.408 20.146,14.408 20.411,14.143 20.411,13.329 20.85,12.89 23.944,12.89 24.724,13.67 25.589,13.67 25.709,13.55 26.347,13.55 v1(26.797,14)
I2C_SDA: J1.39 R10.1 R12.2 U4.C3 | length 25.8
  Top Layer w0.12: R10.1 12.45,15.875 v1(12.45,15.4) ; v2(26.3,16.5) 26.36,16.44 U4.C3 ; R12.2@26.95,14.55 R12.2 ; v1@26.95,14.978 v1(26.972,15) R12.2@26.972,14.572
  Bottom Layer w0.12: J1.39@9.95,15.1 12.066,15.1 12.366,15.4 v1(12.45,15.4) 12.45,14.939 12.743,14.646 13.846,14.646 14.317,14.176 14.317,12.982 14.606,12.692 18.049,12.692 18.429,13.073 18.429,14.282 18.794,14.648 20.246,14.648 20.651,14.242 20.651,13.428 20.949,13.13 23.845,13.13 24.635,13.92 25.352,13.92 26.432,15 ; v2(26.3,16.5) 26.3,15.132 26.432,15 ; v1(26.972,15) 26.432,15
MIC1_P: J1.8 R7.1 U4.G1 | length 13.9
  Top Layer w0.12: v1(24.672,13.05) 24.104,13.618 R7.1 24.104,14.934 24.325,15.154 24.45,15.28 24.736,15.28 24.938,15.482 25.11,15.482 U4.G1
  Bottom Layer w0.12: v1(24.672,13.05) 25.052,13.43 25.49,13.43 25.61,13.31 27.079,13.31 27.575,13.806 27.575,14.686 28.045,15.156 28.045,17.058 28.505,17.518 28.505,18.969 29.436,19.9 J1.8@29.75,19.9
MIC2_P: J1.9 R8.1 U4.E1 | length 10.9
  Top Layer w0.12: U4.E1 25.5,15.252 R8.1 25.984,14.016 v1(25.986,14.016)
  Bottom Layer w0.12: v1(25.986,14.016) 26.008,14.016 26.492,14.5 27.009,14.5 27.805,15.296 27.805,17.157 28.265,17.617 28.265,19.206 28.75,19.691 28.75,20.4 29.45,21.1 29.497,21.1 J1.9@29.75,21.1
MICBIAS: J1.7 R6.1 U4.E3 | length 12.9
  Top Layer w0.12: v1(25.222,13.05) 25.497,13.325 25.497,13.625 26.132,13.625 26.366,13.859 26.366,14.622 26.05,14.937 26.05,15.686 U4.E3
  Bottom Layer w0.15: v1(25.222,13.05) 25.227,13.055 27.185,13.055 27.83,13.7 27.83,14.555 28.3,15.025 28.3,16.952 28.76,17.412 28.76,18.017 29.443,18.7 29.497,18.7 J1.7@29.75,18.7
NetA1_1: A1.1 C5.1 L1.2 | length 3
  Top Layer w0.4: A1.1@15.847,37.002 15.847,36.6 ccw(c17.047,36.6) C5.1@17.047,35.4 ; C5.1 L1.2
NetA1_2: A1.2 L4.2
NetB1_1: B1.1 C31.2 U3.3 U3.7 U3.8 | length 12.8
  Top Layer w0.3: B1.1 12.612,11.975 13,12.362 C31.2 13.575,12.362 ; U3.8 15.229,12.116 13.821,12.116 13.575,12.362 ; v1(16.9,13.365) U3.7 15.047,13.365 13.896,13.365 13.575,13.044 13.575,12.362 ; U3.3@20.85,14.782 v1(20.85,15.2) v1@20.85,15.222 ; U3.3@21.437,14.735 U3.3@21.65,14.735
  Bottom Layer w0.2: v1(16.9,13.365) 16.9,13.8 18.322,15.222 v1@20.85,15.222
NetC1_1: C1.1 U1.11 XT1.1 | length 6.2
  Top Layer w0.12: U1.11 26.924,26 XT1.1@27.524,25.4 ; C1.1 27.599,25.129 XT1.1@27.62,25.15
NetC2_2: C2.2 U1.12 XT1.3 | length 5.2
  Top Layer w0.12: U1.12 23.462,26.4 23.622,26.24 25.585,26.24 25.896,26.552 25.896,27.09 XT1.3@25.95,27.144 ; XT1.3@25.77,27.45 25.773,27.453 C2.2
NetC3_1: C3.1 U2.2 | length 0.8
  Top Layer w0.4: U2.2@21.775,31.56 U2.2 C3.1@21.775,32.31
NetC3_2: C3.2 R1.2 R2.2 RFW.1 T1.1 | length 2.6
  Top Layer w0.3: 21.764,34.509 R1.2@21.764,34.986
  Top Layer w0.4: RFW.1@21.764,34.3 21.764,34.309 21.764,34.509 R1.2@21.764,34.986 ; C3.2@21.775,32.91 T1.1 RFW.1@21.775,34.3
NetC4_1: C4.1 L1.1 R1.1 | length 2.9
  Top Layer w0.4: L1.1@18.397,35.4 C4.1 19.147,35.4 R1.1@21.347,35.4
NetC14_1: C14.1 L3.1 U1.16 | length 4.2
  Top Layer w0.2: U1.16 23.32,28 23.67,28.35 23.67,28.97 23.8,29.1 C14.1 C14.1@24.125,29.125
  Top Layer w0.25: C14.1@24.125,29.125 24.125,29.395 24.271,29.542 25.413,29.542 L3.1
NetC27_1: C27.1 U1.51 | length 1.7
  Top Layer w0.2: 14.754,22 U1.51
  Top Layer w0.25: C27.1@13.836,21.307 C27.1 14.518,22 14.754,22
NetC28_1: C28.1 U1.1 | length 1.3
  Top Layer w0.2: U1.1 23.336,22
  Top Layer w0.25: 23.336,22 23.8,22 C28.1
NetC29_1: C29.1 U1.67 | length 1
  Top Layer w0.2: 21.85,20.95 U1.67
  Top Layer w0.25: C29.1@21.85,20.376 21.85,20.95
NetC32_1: C32.1 U4.F8 | length 1.4
  Top Layer w0.12: C32.1 25.2,18.025 25.43,17.795 U4.F8 U4.F8@25.435,17.261
NetC32_2: C32.2 U4.G7 | length 2.1
  Top Layer w0.12: v1(24.582,17.98) 24.582,18.057 24.7,18.175 C32.2 ; v3(24.6,17.14) 24.736,17.004 U4.G7
  Bottom Layer w0.12: v1(24.582,17.98) 24.591,17.971 24.591,17.149 v3(24.6,17.14)
NetC35_1: C35.1 U4.B6 | length 1.4
  Top Layer w0.076: U4.B6 27.342,16.752
  Top Layer w0.1: 27.342,16.752 27.877,16.752 C35.1@28.037,16.913
NetC37_1: C37.1 C38.1 U4.G5 U4.G9 | length 4.7
  Top Layer w0.12: v1(24.09,18.175) 24.09,17.81 C38.1 24.392,17.508 U4.G9 ; C37.1 24.435,16.26 v1(24.476,16.3) 24.885,16.3 25.085,16.5 U4.G5
  Bottom Layer w0.12: v1(24.09,18.175) 24.09,16.685 v1(24.476,16.3)
NetC39_1: C39.1 R13.1 U4.E7 | length 3.9
  Top Layer w0.12: R13.1 25.595,20.005 25.595,19.93 C39.1 26.05,17.314 U4.E7
NetJ1_1: J1.1@25.572,34.299 R2.1 | length 3.7
  Top Layer w0.4: R2.1@22.197,35.4 23.419,35.4 cw(c23.419,32.86) 25.215,34.656 J1.1@25.572,34.299
NetL2_1: L2.1 U1.54 | length 3.3
  Top Layer w0.2: 16.65,20.8 U1.54
  Top Layer w0.25: L2.1@15.338,19.45 L2.1@15.467,19.579 ; L2.1@15.52,19.457 15.745,19.232 L2.1@16.026,19.232 ; L2.1@15.467,19.579 15.433,19.545 L2.1@15.467,19.579
  Top Layer w0.3: L2.1@15.938,19.332 16.65,20.044 16.65,20.94
NetU1_18: U1.18 U2.6 | length 1.3
  Top Layer w0.2: U1.18 22.25,29.497
  Top Layer w0.4: 22.299,29.546 22.299,30.4
NetU1_21: U1.21 U1.22 U2.4 | length 3.5
  Top Layer w0.2: U1.22 20.65,29.465 ; U1.21 21.05,29.463
  Top Layer w0.25: 20.65,29.465 20.65,30.159 U2.4 ; 21.05,29.463 21.05,30.27 21.276,30.496
PA0/MICBIAS: C40.1 R6.2 R13.2 U1.2 | length 11.8
  Top Layer w0.12: U1.2 23.854,22.4 24.165,22.09 24.871,22.09 24.95,22.011 24.95,20.705 24.726,20.481 24.726,20.426 R13.2 C40.1 24.7,19.205 v1(24.195,18.7) ; v1(24.577,14.869) 24.577,14.123 R6.2@25,13.7
  Bottom Layer w0.12: v1(24.195,18.7) 23.988,18.7 23.597,18.309 23.597,16.39 24.015,15.972 24.015,15.421 24.572,14.865 v1(24.577,14.869)
PA2/MIC2_P: R8.2 U1.4 | length 12.1
  Top Layer w0.12: U1.4 23.733,23.2 24.363,22.57 25.13,22.57 25.435,22.265 25.435,21.29 25.861,20.864 26.315,20.864 26.65,20.53 v1(26.649,20.501) ; R8.2 25.023,14.523 25.023,14.926 v1(25.097,15)
  Bottom Layer w0.12: v1(25.097,15) 25.18,15.083 25.18,16.753 25.27,16.843 25.27,17.453 26.05,18.233 26.05,19.902 v1(26.649,20.501)
PA4/MIC1_P: C39.2 R7.2 U1.3 | length 13.5
  Top Layer w0.12: U1.3 23.794,22.8 24.264,22.33 24.97,22.33 25.195,22.105 25.195,21.18 C39.2 26.505,19.87 v1(26.505,18.9) ; v1(23.602,14.972) 23.602,14.507 R7.2
  Bottom Layer w0.12: v1(23.602,14.972) 24.085,14.489 25.124,14.489 25.477,14.843 25.477,16.209 25.426,16.26 25.426,16.66 25.51,16.743 25.51,17.354 26.505,18.349 v1(26.505,18.9)
PA7/UART_LOG_TXD: J1.19 U1.7 | length 16
  Top Layer w0.12: U1.7 23.606,24.4 23.866,24.14 25.346,24.14 26.161,23.325 v1(26.543,23.325)
  Bottom Layer w0.12: v1@26.577,23.325 26.577,23.381 26.823,23.627 26.823,24.4 27.477,25.054 27.477,30.274 28.81,31.607 28.81,32.51 29.4,33.1 29.497,33.1 J1.19@30.097,33.1 ; J1.19@29.45,33.1 J1.19@29.75,33.1
PA8/UART_LOG_RXD: J1.20 U1.8 | length 15.7
  Top Layer w0.12: U1.8 23.545,24.8 23.946,24.4 25.425,24.4 26.012,23.813 v1(26.33,23.813)
  Bottom Layer w0.12: v1(26.33,23.813) 26.583,24.066 26.583,24.5 27.237,25.153 27.237,30.381 28.563,31.707 28.563,32.646 28.817,32.9 28.817,33.717 J1.20@29.448,34.348
PA12: J1.23 U1.25 | length 12.5
  Top Layer w0.12: v1@11.7,33.3 11.82,33.42 13.91,33.42 14.61,32.72 15.078,32.72 16.723,32.72 18.967,30.476 18.967,30.025 19.45,29.542 U1.25
  Bottom Layer w0.12: J1.23@10.775,34.175 v1@11.676,33.274
  Bottom Layer w0.15: J1.23@9.95,34.3 J1.23@10.775,34.3 ; J1.23@10.775,34.3 10.775,34.175 J1.23@10.775,34.3
  other v1: 11.725,33.323
PA13: J1.24 U1.26 | length 11.6
  Top Layer w0.12: v1(12.042,32.861) 12.361,33.18 13.81,33.18 14.515,32.475 16.553,32.475 18.727,30.302 18.727,29.926 19.05,29.603 U1.26
  Bottom Layer w0.12: J1.24@9.95,33.1 10.497,33.1 11.183,33.1 11.421,32.861 v1(12.042,32.861)
PA14: J1.25 U1.27 | length 11.3
  Top Layer w0.12: v1@11.7,32.32 v1@11.707,32.32 ; v1(11.729,32.399) 12.126,32.399 12.667,32.94 13.711,32.94 14.416,32.235 16.454,32.235 18.487,30.202 18.487,29.827 18.65,29.663 U1.27
  Bottom Layer w0.12: J1.25@9.95,31.9 10.497,31.9 11.231,31.9 v1(11.729,32.399)
PA15: J1.26 U1.28 | length 10.6
  Top Layer w0.12: v1@11.821,31.754 12.767,32.7 13.611,32.7 14.316,31.995 16.355,31.995 18.247,30.103 18.247,29.053 U1.28
  Bottom Layer w0.12: J1.26@10.55,30.7 10.65,30.7 v1@11.762,31.812
  other v1: 11.751,31.824
PA16: J1.27 U1.29 | length 10.7
  Top Layer w0.12: v1(12.95,32.32) 13.652,32.32 14.217,31.755 16.255,31.755 17.85,30.16 U1.29
  Bottom Layer w0.12: J1.27@10.55,29.5 10.65,29.5 11.26,30.11 11.26,30.747 v1@12.823,32.31
PA17: J1.28 U1.30 | length 11.2
  Top Layer w0.12: v1(13.35,31.94) 13.679,31.94 14.103,31.515 16.156,31.515 17.45,30.221 U1.30
  Bottom Layer w0.12: J1.28@10.55,28.3 10.65,28.3 11.5,29.15 11.5,30.648 12.793,31.94 v1(13.35,31.94)
PA18: J1.29 U1.31 | length 11.5
  Top Layer w0.12: v1@12.968,31.56 13.719,31.56 14.004,31.275 16.056,31.275 17.05,30.281 U1.31
  Bottom Layer w0.1: J1.29@10.55,27.1 J1.29@10.65,27.1
  Bottom Layer w0.12: J1.29@10.65,27.1 10.934,27.384 10.934,27.417 11.25,27.733 11.25,28.561 11.74,29.051 11.74,30.521 12.779,31.56 v1(12.95,31.56) v1@12.968,31.56
PA19: J1.30 U1.32 | length 11.8
  Top Layer w0.12: v1(13.35,31.18) 13.495,31.035 15.957,31.035 16.65,30.342 U1.32
  Bottom Layer w0.1: J1.30@10.55,25.9 J1.30@10.65,25.9
  Bottom Layer w0.12: J1.30@10.65,25.9 11.23,26.48 11.23,27.374 11.49,27.634 11.49,28.34 11.98,28.83 11.98,30.403 12.757,31.18 v1(13.35,31.18)
PA25/HSDM: J1.36 U1.40 | length 11.1
  Top Layer w0.12: v1(12.868,26.24) 12.944,26.24 13.104,26.4 U1.40
  Bottom Layer w0.12: J1.36@10.55,18.7 10.65,18.7 11.52,19.57 11.52,21.291 11.98,21.751 11.98,23.472 12.24,23.732 12.24,24.033 13.05,24.843 13.05,26.059 v1(12.868,26.24)
PA26/HSDP: J1.35 U1.39 | length 10.7
  Top Layer w0.12: v1@12.467,26.517 v1(12.467,26.6) 12.558,26.691 14.381,26.691 14.49,26.8 U1.39
  Bottom Layer w0.12: J1.35@10.55,19.9 10.65,19.9 11.28,20.53 11.28,21.391 11.74,21.851 11.74,23.572 12,23.832 12,24.151 12.81,24.961 12.81,25.756 12.467,26.099 v1(12.467,26.6)
PA27/SWD_DATA: J1.31 U1.33 | length 12
  Top Layer w0.12: v1(12.95,30.8) 12.955,30.795 15.858,30.795 16.25,30.403 U1.33
  Bottom Layer w0.12: J1.31@10.55,24.7 10.63,24.7 11.47,25.54 11.47,27.274 11.73,27.534 11.73,28.241 12.22,28.731 12.22,30.07 v1(12.95,30.8)
PA28: J1.34 R4.2 U1.38 | length 10.2
  Top Layer w0.12: v1(12.09,26.961) 12.109,26.98 12.707,26.98 12.756,26.931 13.325,26.931 R4.2@13.569,27.175 ; R4.2@13.6,27.2 U1.38
  Bottom Layer w0.12: J1.34@10.55,21.1 10.65,21.1 11.5,21.95 11.5,23.671 11.76,23.931 11.76,24.269 12.57,25.079 12.57,25.657 12.087,26.14 12.087,26.958 v1(12.09,26.961)
PA30: J1.33 R3.2 U1.36 | length 12.1
  Top Layer w0.12: v1(12.6,28.968) 12.861,28.968 13.443,29.55 13.893,29.55 14.293,29.15 14.293,28.257 14.55,28 U1.36
  Bottom Layer w0.12: J1.33@10.55,22.3 10.65,22.3 11.26,22.91 11.26,23.771 11.52,24.031 11.52,24.376 12.33,25.186 12.33,25.557 11.71,26.177 11.71,27.142 11.97,27.402 11.97,28.02 12.6,28.65 v1(12.6,28.968)
PB1/ADC4: J1.37 U1.41 | length 11.5
  Top Layer w0.12: v1(13.45,26) U1.41
  Bottom Layer w0.12: J1.37@10.55,17.5 10.65,17.5 11.28,18.13 11.28,18.983 11.76,19.463 11.76,21.19 12.22,21.65 12.22,23.373 12.48,23.633 12.48,23.92 13.45,24.89 v1(13.45,26)
PB2/ADC5: J1.42 U1.42 | length 19.7
  Top Layer w0.12: v1(11.74,11.475) 11.74,12.995 11.551,13.184 11.551,25.518 11.773,25.74 12.963,25.74 13.103,25.6 U1.42
  Bottom Layer w0.12: J1.42@9.95,11.5 9.963,11.487 10.5,11.487 11.728,11.487 v1(11.74,11.475)
PB3/SWD_CLK: J1.32 U1.43 | length 5.8
  Top Layer w0.12: v1(11.931,25.36) 14.445,25.36 14.605,25.2 U1.43
  Bottom Layer w0.12: J1.32@10.55,23.5 10.65,23.5 11.28,24.13 11.28,24.709 v1(11.931,25.36)
PB4: J1.41 U1.44 | length 17.3
  Top Layer w0.12: v1(12,13.5) 12,14.91 11.794,15.117 11.794,24.366 12.532,25.105 14.205,25.105 14.51,24.8 U1.44
  Bottom Layer w0.12: J1.41@9.95,12.7 10.497,12.7 10.73,12.7 10.69,12.74 11.45,13.5 v1(12,13.5)
PB5/LP_I2C_SCL: R9.2 U1.45 | length 13.2
  Top Layer w0.12: R9.2 12.034,15.216 12.034,24.267 12.632,24.865 14.105,24.865 14.57,24.4 U1.45
PB6/LP_I2C_SDA: R10.2 U1.46 | length 11.2
  Top Layer w0.12: R10.2@12.377,16.425 12.377,16.797 12.274,16.901 12.274,24.168 12.731,24.625 14.003,24.625 14.62,24.008 15.192,24.008 U1.46
PB7: J1.38 U1.47 | length 11.7
  Top Layer w0.12: v1(13.475,24.233) 13.998,24.233 14.631,23.6 U1.47
  Bottom Layer w0.12: J1.38@9.95,16.3 9.955,16.305 10.698,16.305 10.698,16.401 11.25,16.953 11.25,17.738 11.52,18.008 11.52,18.884 12,19.364 12,21.091 12.46,21.551 12.46,23.21 13.37,24.12 v1@13.455,24.12
PB13/FH_SPI_CLK: U1.57 U3.6 | length 10.1
  Top Layer w0.12: U3.6@14.65,14.735 U3.6@15.25,14.735 ; U3.6 17.752,14.635 18.19,15.073 18.19,19.007 17.85,19.347 U1.57
PB14/FH_SPI_DATA0: U1.56 U3.5 | length 8.7
  Top Layer w0.12: U3.5@14.65,16.005 U3.5@15.25,16.005 ; U3.5 17.546,15.905 17.95,16.309 17.95,18.907 17.61,19.247 17.61,20.415 17.45,20.575 U1.56
PB16/FH_SPI_CS: R14.1 U1.58 U3.1 | length 13.2
  Top Layer w0.12: U1.58 18.25,20.581 18.094,20.425 18.094,19.442 18.43,19.106 18.43,13.216 19.551,12.095 U3.1 ; U3.1@21.05,12.195 R14.1@22.85,12.195
PB17/FH_SPI_DATA1: U1.59 U3.2 | length 10.9
  Top Layer w0.12: U1.59 18.65,20.626 18.378,20.354 18.378,19.497 18.67,19.205 18.67,13.867 19.172,13.365 U3.2 ; U3.2@21.05,13.465 U3.2@21.65,13.465
PB22: J1.4 U1.60 | length 22
  Top Layer w0.12: v1(19.05,14.026) 19.05,19.165 18.632,19.583 18.632,20.268 19.05,20.686 U1.60@19.05,21.35
  Bottom Layer w0.12: v1(19.05,14.026) v1(19.05,14.026) 19.049,12.615 19.494,12.17 25.684,12.17 25.834,12.32 27.531,12.32 28.565,13.354 28.565,14.202 29.463,15.1 29.497,15.1 J1.4@30.097,15.1
PB23: J1.5 U1.61 | length 22.1
  Top Layer w0.12: U1.61 19.46,21.341 19.46,20.72 18.906,20.167 18.906,19.648 19.32,19.234 19.32,14.307 19.511,14.116 v1(19.511,13.752)
  Bottom Layer w0.12: v1(19.511,13.752) 19.511,13.016 20.117,12.41 25.55,12.41 25.7,12.56 27.43,12.56 28.325,13.455 28.325,14.35 28.795,14.82 28.795,15.645 29.45,16.3 J1.5@29.95,16.3
PB26: J1.6 U1.63 | length 22.5
  Top Layer w0.12: v1@19.989,14.128 v1(19.989,14.028) 19.57,14.447 19.57,16.968 20.25,17.648 U1.63
  Bottom Layer w0.12: v1(19.989,14.028) 19.989,13.412 20.751,12.65 25.451,12.65 25.601,12.8 27.321,12.8 28.085,13.564 28.085,14.449 28.555,14.919 28.555,16.658 29.397,17.5 J1.6@30.097,17.5
PB29/AOUTP_R: J1.15 U1.64 | length 19.5
  Top Layer w0.15: U1.64 20.65,20.198 20.532,20.08 20.532,18.274 21.253,17.553 v1(21.67,17.553)
  Bottom Layer w0.15: v1(21.67,17.553) 24.517,20.4 25.532,20.4 26.499,21.368 26.499,21.826 27.762,23.088 27.762,24.218 28.242,24.698 28.242,27.145 29.123,28.026 29.214,28.026 29.488,28.3 J1.15@29.75,28.3
PB31/AOUTP_L: J1.16 U1.65 | length 19.4
  Top Layer w0.12: U1.65 U1.65@21.06,21.341
  Top Layer w0.15: U1.65@21.06,21.341 21.06,20.219 20.802,19.961 20.802,18.562 v1(21.343,18.021)
  Bottom Layer w0.15: v1(21.343,18.021) 21.354,18.033 21.768,18.033 24.405,20.67 25.42,20.67 26.229,21.479 26.229,21.938 27.492,23.2 27.492,24.329 27.972,24.809 27.972,28.075 29.397,29.5 J1.16@29.497,29.5
RESET: C30.1 J1.18 R5.2 U1.6 | length 15.2
  Top Layer w0.12: U1.6 23.667,24 23.767,23.9 25.246,23.9 R5.2@26.373,22.773 ; R5.2@26.421,22.7 C30.1 27.063,22.737 v1(27.063,23.33)
  Bottom Layer w0.12: v1(27.063,23.33) 27.063,24.301 27.717,24.955 27.717,30.167 29.45,31.9 29.497,31.9 J1.18@29.75,31.9
VBATM: C26.1 J1.3@29.497,13.9 J1.3@30.097,13.9 U1.48 | length 32.9
  Top Layer w0.12: v1(12.9,15.026) 12.9,15.76 12.81,15.85 12.81,16.703 12.514,17 12.514,23.954 12.65,24.09 13.071,24.09 C26.1@13.434,23.727 ; v1(17.95,12.07) v1(17.95,13.131)
  Top Layer w0.2: C26.1 14.1,23.7 14.6,23.2 U1.48
  Bottom Layer w0.12: v1(12.9,15.026) 13.806,15.026 14.557,14.275 14.557,13.081 14.705,12.932 17.351,12.932 17.55,13.131 v1(17.95,13.131) ; v1(17.95,12.07) 19.254,12.07 19.394,11.93 25.784,11.93 25.934,12.08 27.63,12.08 29.45,13.9 J1.3@30.05,13.9
VD11: C6.2 C7.1 C8.1 C9.1 C10.1 C11.1 C12.1 C13.1 L2.2 U1.9 U1.14 U1.15 U1.24 U1.35 U1.50 U1.62 | length 110.5
  Top Layer w0.12: C11.1@13.563,29.888 C11.1
  Top Layer w0.2: 14.734,22.4 U1.50 15.61,22.4 ; 14.75,28.4 U1.35 15.733,28.4 15.875,28.258 15.875,22.221 v1@15.875,22.1 ; 15.622,22.4 v1@15.85,22.172 ; v1(16.55,22.1) 16.2,22.45 16.2,28.265 16.317,28.382 19.629,28.382 19.847,28.601 19.847,28.642 19.85,28.645 U1.24 19.85,29.465 ; 19.85,20.95 U1.62 ; U1.9 23.322,25.2 ; U1.14 23.33,27.2 ; U1.15 23.33,27.6
  Top Layer w0.25: C13.1 14.16,22.2 14.36,22.4 14.734,22.4 ; C11.1@13.711,30.082 C11.1@13.718,30.082 ; C11.1@13.79,30.036 C11.1@13.79,30.115 ; C11.1@13.881,30.036 14.598,29.318 14.598,28.552 14.75,28.4 14.762,28.4 ; v1@15.85,22.246 15.875,22.221 15.923,22.172 v1(15.923,22.1) ; v1(19.286,19.845) C12.1@19.776,19.845 ; C10.1@19.32,30.224 19.847,29.697 19.847,29.468 ; C12.1 19.85,19.9 19.85,20.95 ; 23.322,25.2 23.4,25.2 23.442,25.158 23.681,25.158 23.739,25.1 v1@23.78,25.1 ; 23.33,27.2 23.9,27.2 24.2,27.5 v1(24.2,27.7) ; 23.33,27.6 23.433,27.6 24.1,28.267 v1(24.1,28.6) ; v1(23.795,25.1) 23.798,25.103 C7.1
  Top Layer w0.8: C6.2@13.425,17.75 L2.2@15.797,17.75
  Bottom Layer w0.15: v1(13.55,17.1) v1@13.725,17.1 ; 19.951,19.976 18.4,18.425 18.4,17.32 17.48,16.4 14.825,16.4 14.268,16.957 13.868,16.957 14.7,16.125 17.6,16.125 18.675,17.2 18.675,18.325 20.05,19.7 20.525,19.7 22.875,22.05 22.875,26.975 23.6,27.7 v1(24.2,27.7) ; 19.953,19.975 20.425,19.975 ; 20.424,19.976 22.6,22.153 22.6,27.1 v1(24.1,28.6)
  Bottom Layer w0.25: v1@13.075,17.279 13.075,17.978 13.846,18.75 13.846,20.432 14.409,20.995 14.409,21.615 14.894,22.1 v1(15.923,22.1) ; v1@13.324,17.072 14.622,15.775 17.725,15.775 19,17.05 19,18.15 20.15,19.3 21.4,19.3 23.78,21.68 23.78,25.085 v1(23.795,25.1) ; v1@13.352,17.1 v1@13.497,17.1 ; v1(13.55,17.1) v1@13.497,17.1 ; v1@13.925,17.1 v1(13.95,17.1) 14.6,17.1 14.845,16.855 17.484,16.855 18.05,17.421 18.05,18.609 v1(19.286,19.845) ; v1(16.55,22.1) 16.087,21.637 15.033,21.637 14.762,21.365 14.762,20.804 14.197,20.239 14.197,18.5 13.497,17.8 v1@13.497,17.1
  Bottom Layer w0.4: v1@13.9,17.1 v1@13.925,17.1
  other v1: 13.15,17.1
VDD: B1.2 C15.1 C16.1 C17.1 C18.1 C19.1 C20.1 C21.1 C22.1 C23.1 C24.1 C25.1 C33.1 C34.1 C41.2 J1.1@29.497,11.5 J1.1@30.097,11.5 L3.2 R3.1 R5.1 R11.1 R12.1 R14.2 U1.5 U1.10 U1.13 U1.17 U1.23 U1.34 U1.37 U1.49 U1.52 U1.55 U1.66 U4.B4 U4.F6 | length 158.4
  Top Layer w0.076: 24.703,16.752 U4.F6@25.426,16.752 ; U4.B4 27.286,16.248
  Top Layer w0.12: C21.1 13.776,28.201 C21.1@13.85,28.275
  Top Layer w0.2: 14.743,27.6 U1.37 ; 14.751,22.8 U1.49 ; U1.34 15.85,29.478 ; 21.45,20.95 U1.66 ; U1.5 23.341,23.6 ; U1.10 23.325,25.6 ; U1.13 23.313,26.8 ; U1.17 U1.17@23.23,28.4 ; 24.736,16.724 24.396,16.724 C33.1 24.1,16.909 23.841,16.65 23.3,16.65 23.15,16.5 23.15,13.908 24.64,12.418 25.45,12.418
  Top Layer w0.25: v1(12.897,19.9) 13.197,19.9 13.375,20.078 13.375,20.375 C23.1 13.814,20.4 14.821,21.407 14.821,21.471 14.85,21.5 U1.52@15.797,21.5 ; C22.1 13.549,22.808 v1(14.099,22.808) 14.106,22.8 14.751,22.8 ; C21.1@13.776,28.201 14.378,27.6 14.743,27.6 ; v1@15.728,30.374 15.849,30.253 15.849,29.48 ; 21.45,20.95 21.45,20.12 21.558,20.012 C25.1@21.558,19.77 ; 23.313,26.8 23.6,26.8 v1(23.65,26.75) 23.796,26.604 C18.1 ; 23.325,25.6 23.646,25.6 v1(23.649,25.603) ; 23.341,23.6 23.554,23.6 23.629,23.525 24.075,23.525 C15.1 ; v1@23.649,25.6 C17.1 ; v1(24.1,30.5) v1(24.6,30.5) 26.068,30.5 L3.2@26.55,30.018
  Top Layer w0.3: v1(13.497,16.1) v1@13.52,16.123 ; R3.1@13.601,29.143 13.85,28.894 v1(13.85,28.7) C21.1@13.85,28.275 ; 17.072,20.95 17.072,19.228 17.05,19.207 17.55,18.707 v1(17.55,18.05) ; 20.25,29.468 C20.1@20.25,30.25 ; v1(21.197,19.745) v1@21.197,19.7 ; C25.1@21.434,19.7 v1@21.197,19.7 ; U1.17@23.247,28.45 23.3,28.503 23.3,29.2 C19.1 v1(24.1,30.5) ; v1@23.755,11.6 23.755,12.626 22.725,13.656 22.725,16.275 22.23,16.77 22.23,17.979 21.197,19.012 v1@21.197,19.7 ; C15.1 24.1,23.3 24.5,22.9 25.509,22.9 25.838,22.571 25.838,22.462 26.1,22.2 26.724,22.2 28.095,20.829 28.095,19.185 27.885,18.975 v1(27.885,18.534) v1(27.885,18.1) ; v1(27.425,16.1) C34.1
  Top Layer w0.4: v1@13.52,16.123 13.976,16.579 16.964,16.579 17.55,17.165 v1(17.55,17.55) v1(17.55,18.05) ; v1(14.906,33.15) 18.288,33.15 19.767,31.671 19.767,30.446 19.963,30.25 C20.1@20.197,30.25 ; C41.2@26.26,12.13 26.285,12.13 26.475,12.32 26.475,12.345 27.515,13.385 27.515,14.5 27.515,16.01 v1(27.425,16.1)
  Top Layer w0.6: B1.2 v1(13.225,13.6) 13.52,13.895 13.52,16.123 13.52,16.159 v1@13.29,16.389
  Bottom Layer w0.15: v1(21.197,19.745) 21.197,19.972 23.145,21.92 23.145,26.245 v1(23.65,26.75) ; v1@21.3,19.7 23.4,21.8 23.4,25.354 v1(23.649,25.603)
  Bottom Layer w0.25: v1(13.85,28.7) 14.45,28.1 14.45,23.159 v1(14.099,22.808) v1@14.106,22.8
  Bottom Layer w0.253: v1@13.105,16.389 v1(13.211,16.389) ; v1@13.159,16.338 12.54,16.338 12.197,16.681 12.197,18.5 12.897,19.2 v1(12.897,19.9) 12.897,20.857 13.4,21.36 13.4,22.094 v1@14.106,22.8
  Bottom Layer w0.3: v1(17.55,17.55) v1(17.55,18.05) 17.55,18.773 19.114,20.337 20.297,20.337 22.25,22.29 22.25,27.475 24.1,29.325 v1(24.1,30.5) v1(24.6,30.5) ; J1.1@29.55,11.5 J1.1@30.15,11.5
  Bottom Layer w0.4: v1@13.105,16.389 12.63,16.864 12.63,18.233 13.4,19.003 13.4,20.682 13.963,21.245 13.963,21.866 14.877,22.78 14.877,29.493 15.176,29.793 ; v1(15.4,33.15) v1(14.906,33.15) 14.906,30.791 15.176,30.52 15.176,29.793 ; v1(15.75,30.366) 15.176,29.793 ; v1(27.425,16.1) 27.425,17.315 27.885,17.775 v1(27.885,18.1) v1(27.885,18.534)
  Bottom Layer w0.5: v1(13.211,16.389) 13.497,16.103 v1(13.497,16.1)
  Bottom Layer w0.8: v1@13.401,13.773 12.9,13.272 v1(12.9,13.25) 12.9,12.125 13.495,11.53 17.02,11.53 17.2,11.35 23.925,11.35 ; v1@26.174,11.5 29.497,11.5 J1.1@29.55,11.5
  other v1: 26.05,11.445 26.45,11.445 26.85,11.445 23.23,11.5 23.65,11.5 24.066,11.5 13.482,13.94
VREG: C36.1 J1.14 U4.G3 | length 15.3
  Top Layer w0.2: C36.1 24.303,15.687 24.512,15.687 v1(24.55,15.725) ; v1@24.55,15.7 24.836,15.986 25.11,15.986 U4.G3
  Bottom Layer w0.2: v1(24.55,15.725) 24.563,15.713 24.9,16.05 24.9,16.869 24.99,16.959 24.99,17.58 25.75,18.34 25.75,20.201 26.473,20.924 26.814,21.265 26.814,21.7 28.057,22.943 28.057,24.095 28.537,24.575 28.537,26.205 29.432,27.1 J1.14@30.097,27.1
pads on no net: U1.19 U4.A1 U4.A3 U4.B2 U4.C7 U4.F2

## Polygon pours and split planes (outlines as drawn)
GND on Bottom Layer "Bottom Layer-GND" (solid, remove dead copper, pour order 0): 10,10 10,43 29.999,43 29.997,10
GND on Top Layer "Bottom Layer-GND" (solid, remove dead copper, pour order 1): 10,10 10,43 29.999,43 29.997,10

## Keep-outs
Keep-Out Layer:
  the board outline again, w0.2

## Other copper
Top Layer:
  rectangle net GND: 22.5,21 23.4,21.5
  region net GND: 13.674,42.07 13.674,42.776 13.494,42.776 13.494,42.07
  pour cut-out: 22.35,21.6 22.5,21.6 22.5,21.425 22.35,21.425
  pour cut-out: 22.35,21.225 22.5,21.225 22.5,21.05 22.35,21.05
  pour cut-out: 26.675,12.8 27.2,12.8 27.2,11.1 26.675,11.1
  region: 21.66,43.719
  region net GND: 16.037,36.23
  pour cut-out: 12.697,18.15 12.697,18.65 14.497,18.65 14.497,18.15
  pour cut-out: 21.294,30.514 21.296,31.91 21.598,31.911 22.199,31.911 22.205,31.172 22.21,30.51
  pour cut-out: 19.997,30.398 19.997,31.6 20.693,31.6 20.699,30.398
  pour cut-out: 21.35,28.55 21.35,30 21.95,30 21.95,28.55
  pour cut-out: 20.975,31.059 20.975,31.359 22.6,31.359 22.6,31.059
  pour cut-out: 24.35,23.448 28.25,23.448 28.25,27.85 26.731,29.369 24.35,29.404
  pour cut-out: 14.397,16.8 14.397,20 16.697,20 16.697,16.8
  region net VD11: 12.997,18.13 12.997,16.9 14.157,16.9 14.157,17.18 13.768,17.568 13.768,18.13
  region net VDD: 25.88,12.525 25.875,11.2 27.05,11.2 27.05,11.6 26.68,11.97 26.68,12.525
  region net VDD: 26.658,11.7 26.658,12.525 25.225,12.525 24.56,11.86 22.675,11.86 22.675,11.375 22.85,11.2 24.93,11.2 25.43,11.7
  region: 26.65,11.645
  region net NetL2_1: 15.633,19.683 16.55,20.6 16.55,21.4 16.75,21.4 16.75,20 15.633,18.883
  region: 15.932,19.9
  region: 15.932,20.007
  pour cut-out: 15.6,20.9 22.15,20.9 22.15,21.675 21.825,22 15.6,22
  pour cut-out: 23.2,21.75 23.2,28.4 22.25,28.4 22.25,28.384 22.25,22.025 22.525,21.75
  pour cut-out: 22.25,29.05 15.85,29.05 15.85,28.4 15.866,28.4 22.25,28.4 22.25,29.05
  pour cut-out: 26.919,16.591 26.919,16.409 26.856,16.409 26.829,16.436 26.829,16.501
  pour cut-out: 21.545,15.538 21.544,16.478 21.873,16.478 21.874,15.538 21.547,15.538 21.575,15.576
  pour cut-out: 20.89,15.529 20.89,16.468 21.218,16.468 21.219,15.529 20.892,15.528 20.921,15.566
  pour cut-out: 20.122,15.525 20.121,16.464 20.45,16.464 20.451,15.525 20.124,15.524 20.152,15.563
  pour cut-out: 13.197,29.793 13.197,30.393 13.497,30.393 13.497,29.793
  pour cut-out: 13.197,27.893 13.197,28.493 13.497,28.493 13.497,27.893
  pour cut-out: 13.247,21 13.247,21.6 13.547,21.6 13.547,21
  pour cut-out: 17.257,18.647 16.657,18.647 16.657,18.947 17.257,18.947
Bottom Layer:
  region net GND: 27.913,12.071 28.997,12.071 28.997,13.099 28.941,13.099
  pour cut-out: 28.7,11.9 28.7,30.2 29.997,30.2 29.997,11.9
  region net VD11: 13.05,16.9 12.95,16.996 12.95,17.36 14.1,17.36 14.1,16.957 14.043,16.9
  pour cut-out: 9.963,11.487 9.95,11.5 9.95,34.922 10.028,35 11.3,35 11.304,10.804 9.97,10.796
  pour cut-out: 30.096,34.299 30.097,35.002 28.792,34.998 28.767,31.203 30.096,31.199
  pour cut-out: 20.097,17.1

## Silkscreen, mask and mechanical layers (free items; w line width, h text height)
Top Overlay:
  circle w0.254: c27.515,15.078 r0.113
  region: 23.628,37.781
Top Solder:
  text "EMC3380" at 19.5,38.5 h1
  text "V1.2 XXXX" at 19.5,36.9 h0.8
Mechanical 2:
  pour cut-out: 16.497,36.9

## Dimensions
10,43 to 29.999,43 on Top Overlay
29.997,10 to 29.997,43 on Top Overlay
